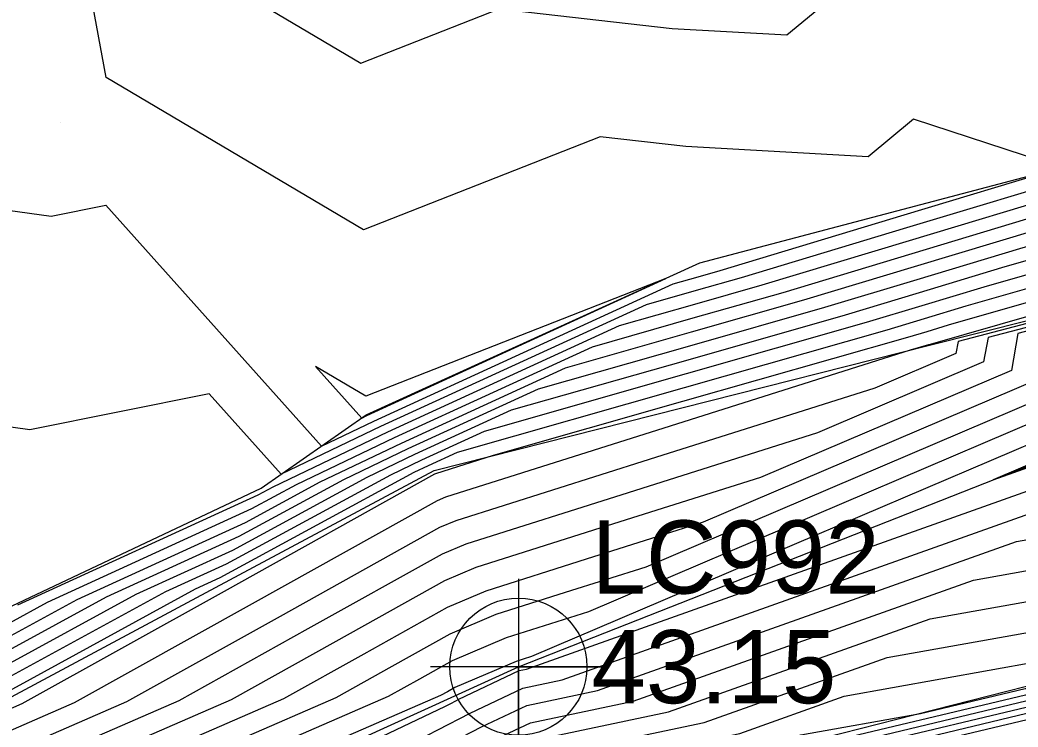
# Model space of a CAD drawing. Extents: x 2188792 to 2191981, y 386090 to 389710.
# Drawn here: x 2190178.31 to 2190212.42, y 387929.77 to 387953.95 of the extents above; entities that cross this region are included whole.
import ezdxf

# ---------------------------------------------------------------- set-up
doc = ezdxf.new("R2010")
doc.units = 0
for name, color, linetype in [('DTM Contours Major', 7, 'Continuous'), ('DTM Contours Minor', 7, 'Continuous'), ('Exist DTM Breakline Underwater', 7, 'Continuous'), ('Exist DTM Breakline Underwater Cogo Elevation', 7, 'Continuous'), ('Exist DTM Breakline Underwater Cogo Number', 7, 'Continuous'), ('Exist DTM Breakline Underwater Cogo Point CELL', 7, 'Continuous'), ('Exist DTM QL2 LIDAR Elevation Point', 7, 'Continuous'), ('PH Exist DTM Breakline', 7, 'Continuous')]:
    doc.layers.add(name, color=color, linetype=linetype)

msp = doc.modelspace()

# ---------------------------------------------------------------- linework, layer by layer
at = {"layer": 'DTM Contours Major'}
for points in [[(2190238.761, 387953.476), (2190238.236, 387953.33), (2190231.049, 387951.931), (2190229.826, 387951.794), (2190223.241, 387950.56), (2190223.252, 387950.255), (2190221.331, 387949.704), (2190216.099, 387948.12), (2190213.685, 387947.428), (2190208.783, 387945.95), (2190204.376, 387944.62), (2190201.304, 387943.745), (2190197.863, 387942.764), (2190191.097, 387939.659), (2190187.751, 387938.056), (2190186.22, 387937.225), (2190179.234, 387934.025), (2190177.951, 387933.325)], [(2190241.141, 387952.366), (2190236.279, 387951.015), (2190233.163, 387950.409), (2190227.76, 387949.804), (2190225.079, 387949.301), (2190225.113, 387948.341), (2190219.055, 387946.601), (2190217.247, 387946.054), (2190210.637, 387944.16), (2190209.214, 387943.73), (2190207.934, 387943.344), (2190201.011, 387941.371), (2190193.254, 387939.16), (2190192.262, 387938.705), (2190191.772, 387938.47), (2190185.14, 387934.868), (2190184.293, 387934.48), (2190177.559, 387930.807)], [(2190243.465, 387950.942), (2190236.16, 387948.641), (2190229.647, 387946.589), (2190224.024, 387945.428), (2190217.646, 387943.561), (2190216.945, 387944.409), (2190212.415, 387943.221), (2190212.19, 387941.963), (2190203.611, 387938.301), (2190198.377, 387936.644), (2190193.887, 387935.221), (2190192.821, 387934.763), (2190189.103, 387932.693), (2190185.528, 387930.702), (2190172.055, 387924.838)], [(2190239.074, 387945.134), (2190217.532, 387940.686), (2190217.208, 387940.591), (2190216.993, 387940.852), (2190216.931, 387940.51), (2190211.569, 387938.221), (2190216.791, 387940.078), (2190217.034, 387940.122), (2190217.401, 387939.598), (2190217.247, 387940.318), (2190217.643, 387940.231), (2190218.033, 387940.301), (2190242.904, 387941.223)], [(2190174.772, 387918.95), (2190187.655, 387925.086), (2190191.189, 387926.924), (2190194.861, 387928.834), (2190195.881, 387929.317), (2190200.477, 387930.285), (2190209.419, 387933.465), (2190214.208, 387934.324), (2190215.059, 387933.111), (2190219.916, 387934.166), (2190219.005, 387935.394), (2190218.404, 387938.199), (2190226.213, 387936.479), (2190233.879, 387937.854), (2190238.048, 387938.009), (2190238.066, 387937.699), (2190244.835, 387939.381)], [(2190175.323, 387915.538), (2190181.724, 387918.921), (2190182.593, 387919.342), (2190188.861, 387922.648), (2190189.628, 387923.046), (2190195.733, 387926.265), (2190196.621, 387926.724), (2190203.158, 387928.251), (2190204.711, 387928.684), (2190206.464, 387929.173), (2190212.686, 387930.663), (2190215.555, 387930.653), (2190220.883, 387931.821), (2190224.858, 387931.651), (2190229.111, 387932.482), (2190232.668, 387933.178), (2190238.216, 387935.813), (2190241.557, 387936.557)]]:
    msp.add_lwpolyline(points, dxfattribs=at)
at = {"layer": 'DTM Contours Minor'}
for points in [[(2190208.525, 387947.281), (2190213.89, 387948.9), (2190208.847, 387950.558), (2190207.29, 387949.272), (2190201.069, 387949.623), (2190198.133, 387949.956), (2190190.044, 387946.776), (2190181.258, 387951.986), (2190179.765, 387960.073)], [(2190184.826, 387955.515), (2190189.959, 387952.472), (2190194.684, 387954.329), (2190200.594, 387953.658), (2190204.514, 387953.437), (2190209.678, 387957.701)], [(2190227.6, 387957.129), (2190234.774, 387953.043), (2190230.626, 387952.236), (2190230.239, 387952.193), (2190222.873, 387950.812), (2190222.879, 387950.638), (2190221.786, 387950.324), (2190215.869, 387948.533), (2190214.294, 387948.082), (2190208.697, 387946.394), (2190203.664, 387944.875), (2190201.363, 387944.219), (2190198.785, 387943.484), (2190190.864, 387939.85), (2190186.947, 387937.973), (2190186.437, 387937.696), (2190178.222, 387933.934)], [(2190149.752, 387955.21), (2190140.061, 387950.046), (2190143.481, 387946.538), (2190148.473, 387940.365), (2190144.823, 387935.32), (2190139.837, 387929.999), (2190143.707, 387917.215), (2190148.398, 387918.499), (2190151.676, 387919.993), (2190159.372, 387924.657), (2190150.776, 387939.385), (2190150.697, 387939.981), (2190169.786, 387948.252), (2190170.884, 387948.414), (2190179.374, 387947.236), (2190181.243, 387947.61), (2190188.609, 387939.375), (2190190.398, 387940.232), (2190200.628, 387944.926), (2190201.48, 387945.169), (2190202.241, 387945.386), (2190208.525, 387947.281)], [(2190216.682, 387955.398), (2190221.76, 387953.676), (2190225.395, 387951.605), (2190222.506, 387951.063), (2190222.507, 387951.021), (2190222.242, 387950.945), (2190215.639, 387948.946), (2190214.904, 387948.736), (2190208.611, 387946.838), (2190202.953, 387945.131), (2190201.422, 387944.694), (2190199.706, 387944.205), (2190190.631, 387940.041), (2190187.233, 387938.413), (2190184.778, 387941.158), (2190178.644, 387939.932), (2190174.81, 387940.464)], [(2190239.237, 387953.254), (2190237.845, 387952.867), (2190231.472, 387951.627), (2190229.413, 387951.396), (2190223.608, 387950.308), (2190223.624, 387949.873), (2190220.876, 387949.083), (2190216.328, 387947.707), (2190213.075, 387946.775), (2190208.869, 387945.506), (2190205.087, 387944.365), (2190201.246, 387943.27), (2190196.941, 387942.043), (2190191.33, 387939.468), (2190188.555, 387938.139), (2190186.004, 387936.753), (2190180.245, 387934.116), (2190177.873, 387932.822)], [(2190239.713, 387953.032), (2190237.453, 387952.404), (2190231.894, 387951.323), (2190228.999, 387950.998), (2190223.976, 387950.056), (2190223.996, 387949.49), (2190220.421, 387948.463), (2190216.558, 387947.293), (2190212.465, 387946.121), (2190208.955, 387945.062), (2190205.799, 387944.11), (2190201.187, 387942.795), (2190196.019, 387941.322), (2190191.563, 387939.277), (2190189.359, 387938.222), (2190185.788, 387936.282), (2190181.257, 387934.207), (2190177.794, 387932.318)], [(2190240.665, 387952.588), (2190236.67, 387951.478), (2190232.74, 387950.714), (2190228.173, 387950.202), (2190224.711, 387949.553), (2190224.741, 387948.724), (2190219.51, 387947.221), (2190217.017, 387946.467), (2190211.246, 387944.813), (2190209.128, 387944.174), (2190207.222, 387943.599), (2190201.07, 387941.846), (2190194.175, 387939.88), (2190192.029, 387938.896), (2190190.968, 387938.387), (2190185.356, 387935.339), (2190183.281, 387934.389), (2190177.638, 387931.31)], [(2190240.189, 387952.81), (2190237.062, 387951.941), (2190232.317, 387951.018), (2190228.586, 387950.6), (2190224.344, 387949.805), (2190224.368, 387949.107), (2190219.965, 387947.842), (2190216.788, 387946.88), (2190211.856, 387945.467), (2190209.041, 387944.618), (2190206.51, 387943.855), (2190201.128, 387942.32), (2190195.097, 387940.601), (2190191.796, 387939.086), (2190190.164, 387938.304), (2190185.572, 387935.811), (2190182.269, 387934.298), (2190177.716, 387931.814)], [(2190241.616, 387952.144), (2190235.887, 387950.552), (2190233.585, 387950.105), (2190227.346, 387949.406), (2190225.447, 387949.05), (2190225.485, 387947.958), (2190218.6, 387945.98), (2190217.477, 387945.64), (2190210.027, 387943.506), (2190209.3, 387943.286), (2190208.645, 387943.089), (2190200.952, 387940.896), (2190194.479, 387939.051), (2190192.511, 387938.427), (2190192.475, 387938.412), (2190185.286, 387934.409), (2190178.375, 387930.561), (2190176.934, 387929.934)], [(2190242.092, 387951.922), (2190235.496, 387950.09), (2190234.008, 387949.8), (2190226.933, 387949.008), (2190225.814, 387948.798), (2190225.858, 387947.575), (2190218.144, 387945.36), (2190217.706, 387945.227), (2190209.418, 387942.852), (2190209.386, 387942.842), (2190209.357, 387942.834), (2190208.733, 387942.656), (2190200.532, 387940.058), (2190192.855, 387937.626), (2190192.561, 387937.5), (2190186.241, 387933.98), (2190180.163, 387930.596), (2190175.714, 387928.66)], [(2190243.044, 387951.478), (2190237.242, 387949.866), (2190234.984, 387949.155), (2190227.762, 387946.88), (2190225.322, 387946.376), (2190217.734, 387944.155), (2190217.33, 387944.644), (2190211.391, 387943.086), (2190211.242, 387942.254), (2190205.567, 387939.832), (2190199.096, 387937.782), (2190193.543, 387936.023), (2190192.735, 387935.675), (2190188.149, 387933.122), (2190183.739, 387930.667), (2190173.274, 387926.112)], [(2190242.568, 387951.7), (2190235.104, 387949.627), (2190234.431, 387949.496), (2190226.52, 387948.609), (2190226.182, 387948.546), (2190226.23, 387947.193), (2190222.987, 387946.261), (2190217.822, 387944.749), (2190217.715, 387944.878), (2190210.367, 387942.951), (2190210.294, 387942.545), (2190207.523, 387941.362), (2190199.814, 387938.92), (2190193.199, 387936.824), (2190192.648, 387936.588), (2190187.195, 387933.551), (2190181.951, 387930.632), (2190174.494, 387927.386)], [(2190243.847, 387950.177), (2190237.337, 387948.126), (2190231.533, 387946.298), (2190222.725, 387944.479), (2190217.559, 387942.967), (2190216.56, 387944.175), (2190213.439, 387943.356), (2190213.139, 387941.672), (2190201.654, 387936.771), (2190197.659, 387935.505), (2190194.231, 387934.419), (2190192.908, 387933.851), (2190190.057, 387932.264), (2190187.316, 387930.737), (2190170.835, 387923.564)], [(2190244.228, 387949.412), (2190238.513, 387947.612), (2190233.418, 387946.007), (2190221.427, 387943.531), (2190217.471, 387942.373), (2190216.176, 387943.941), (2190214.464, 387943.492), (2190214.087, 387941.382), (2190199.698, 387935.241), (2190196.941, 387934.367), (2190194.575, 387933.618), (2190192.995, 387932.939), (2190191.011, 387931.835), (2190189.104, 387930.773), (2190169.615, 387922.29)], [(2190239.69, 387947.098), (2190235.303, 387945.716), (2190220.129, 387942.582), (2190217.384, 387941.779), (2190215.791, 387943.706), (2190215.488, 387943.627), (2190215.035, 387941.091), (2190197.741, 387933.71), (2190196.222, 387933.229), (2190194.919, 387932.816), (2190193.081, 387932.027), (2190191.965, 387931.405), (2190190.892, 387930.808), (2190168.395, 387921.016)], [(2190240.867, 387946.584), (2190237.189, 387945.425), (2190218.831, 387941.634), (2190217.296, 387941.185), (2190216.273, 387942.423), (2190215.983, 387940.8), (2190195.785, 387932.18), (2190195.504, 387932.091), (2190195.263, 387932.015), (2190193.168, 387931.115), (2190192.919, 387930.976), (2190192.68, 387930.843), (2190167.175, 387919.742)], [(2190190.165, 387940.422), (2190200.385, 387945.112), (2190190.129, 387941.081), (2190188.405, 387942.103), (2190189.985, 387940.336), (2190190.165, 387940.422)], [(2190167.739, 387918.52), (2190192.822, 387930.467), (2190193.059, 387930.59), (2190193.305, 387930.718), (2190195.37, 387931.698), (2190195.617, 387931.749), (2190215.316, 387938.755), (2190216.469, 387938.962), (2190218.21, 387936.481), (2190217.478, 387939.895), (2190219.357, 387939.481), (2190221.202, 387939.812), (2190241.932, 387940.58)], [(2190169.497, 387918.627), (2190191.531, 387929.122), (2190192.591, 387929.674), (2190193.694, 387930.247), (2190195.498, 387931.103), (2190196.832, 387931.383), (2190213.842, 387937.433), (2190215.903, 387937.803), (2190217.685, 387935.264), (2190218.699, 387935.484), (2190218.509, 387935.741), (2190217.71, 387939.471), (2190221.071, 387938.73), (2190224.371, 387939.322), (2190240.961, 387939.937)], [(2190171.256, 387918.735), (2190190.239, 387927.777), (2190192.124, 387928.757), (2190194.083, 387929.776), (2190195.625, 387930.507), (2190198.047, 387931.017), (2190212.368, 387936.11), (2190215.338, 387936.643), (2190216.809, 387934.546), (2190219.105, 387935.045), (2190218.674, 387935.625), (2190217.941, 387939.047), (2190222.785, 387937.98), (2190227.54, 387938.833), (2190239.99, 387939.294)], [(2190176.531, 387919.057), (2190186.364, 387923.741), (2190190.722, 387926.007), (2190195.25, 387928.362), (2190196.009, 387928.722), (2190201.693, 387929.919), (2190207.945, 387932.143), (2190213.642, 387933.165), (2190214.184, 387932.394), (2190220.321, 387933.727), (2190219.17, 387935.278), (2190218.635, 387937.775), (2190227.927, 387935.728), (2190237.048, 387937.365), (2190237.077, 387937.366), (2190237.077, 387937.364), (2190237.167, 387937.387), (2190244.751, 387939.075)], [(2190173.014, 387918.842), (2190188.947, 387926.431), (2190191.657, 387927.841), (2190194.472, 387929.305), (2190195.753, 387929.912), (2190199.262, 387930.651), (2190210.894, 387934.788), (2190214.773, 387935.484), (2190215.934, 387933.829), (2190219.51, 387934.606), (2190218.839, 387935.509), (2190218.172, 387938.623), (2190224.499, 387937.229), (2190230.71, 387938.344), (2190239.019, 387938.652)], [(2190178.289, 387919.165), (2190185.072, 387922.396), (2190190.254, 387925.091), (2190195.639, 387927.891), (2190196.136, 387928.127), (2190202.908, 387929.553), (2190206.471, 387930.82), (2190213.077, 387932.005), (2190213.308, 387931.676), (2190220.727, 387933.288), (2190219.335, 387935.163), (2190218.866, 387937.352), (2190228.468, 387935.236), (2190223.124, 387933.808), (2190228.954, 387934.948), (2190235.975, 387936.321), (2190237.355, 387936.977), (2190243.953, 387938.445)], [(2190173.758, 387916.019), (2190180.047, 387919.272), (2190183.78, 387921.05), (2190189.787, 387924.174), (2190196.028, 387927.42), (2190196.264, 387927.532), (2190204.123, 387929.187), (2190204.997, 387929.497), (2190209.081, 387930.23), (2190212.659, 387931.087), (2190212.983, 387931.086), (2190220.82, 387932.805), (2190221.99, 387932.754), (2190229.006, 387934.126), (2190234.873, 387935.273), (2190237.642, 387936.589), (2190243.154, 387937.816)], [(2190174.734, 387915.723), (2190181.806, 387919.38), (2190182.488, 387919.705), (2190189.319, 387923.258), (2190192.136, 387924.723), (2190196.323, 387926.931), (2190196.401, 387926.971), (2190203.97, 387928.739), (2190204.595, 387928.913), (2190205.302, 387929.11), (2190212.673, 387930.875), (2190214.269, 387930.87), (2190220.852, 387932.313), (2190223.424, 387932.203), (2190229.059, 387933.304), (2190233.77, 387934.226), (2190237.929, 387936.201), (2190242.356, 387937.186)], [(2190175.67, 387915.423), (2190181.112, 387918.299), (2190183.101, 387919.263), (2190188.402, 387922.059), (2190189.991, 387922.882), (2190195.144, 387925.599), (2190196.84, 387926.478), (2190202.346, 387927.764), (2190204.826, 387928.455), (2190207.627, 387929.236), (2190212.7, 387930.451), (2190216.841, 387930.436), (2190220.915, 387931.33), (2190226.292, 387931.099), (2190229.164, 387931.66), (2190231.565, 387932.13), (2190238.503, 387935.425), (2190240.759, 387935.927)], [(2190176.017, 387915.308), (2190180.5, 387917.677), (2190183.609, 387919.184), (2190187.944, 387921.47), (2190190.353, 387922.718), (2190194.554, 387924.933), (2190197.06, 387926.231), (2190201.535, 387927.276), (2190204.941, 387928.226), (2190208.789, 387929.299), (2190212.714, 387930.239), (2190218.127, 387930.22), (2190220.946, 387930.838), (2190227.727, 387930.547), (2190229.217, 387930.839), (2190230.462, 387931.082), (2190238.79, 387935.037)], [(2190176.364, 387915.193), (2190179.888, 387917.055), (2190184.117, 387919.105), (2190187.486, 387920.881), (2190190.715, 387922.554), (2190193.964, 387924.267), (2190197.28, 387925.985), (2190200.723, 387926.789), (2190205.056, 387927.997), (2190209.951, 387929.362), (2190212.727, 387930.027), (2190219.412, 387930.003), (2190220.977, 387930.346), (2190229.161, 387929.995), (2190229.269, 387930.017), (2190229.36, 387930.034), (2190239.077, 387934.649)]]:
    msp.add_lwpolyline(points, dxfattribs=at)
at = {"layer": 'Exist DTM Breakline Underwater'}
msp.add_lwpolyline([(2190165.897, 387918.407), (2190195.341, 387931.833), (2190217.185, 387940.432), (2190258.084, 387945.215), (2190309.218, 387932.714), (2190343.089, 387929.481), (2190375.21, 387918.126)], dxfattribs=at)
at = {"layer": 'Exist DTM Breakline Underwater Cogo Point CELL'}
msp.add_lwpolyline([(2190195.341, 387934.833), (2190195.341, 387928.833), (2190195.341, 387931.833), (2190198.341, 387931.833), (2190192.341, 387931.833)], dxfattribs=at)
msp.add_circle((2190195.341, 387931.833), 2.344, dxfattribs=at)
at = {"layer": 'Exist DTM QL2 LIDAR Elevation Point'}
msp.add_line((2190179.694, 387950.438), (2190179.694, 387950.438), dxfattribs=at)
at = {"layer": 'PH Exist DTM Breakline'}
for points in [[(2190109.829, 387900.589), (2190117.728, 387904.556), (2190125.627, 387908.523), (2190133.526, 387912.49), (2190141.824, 387916.341), (2190150.122, 387920.192), (2190161.927, 387925.89), (2190169.542, 387929.904), (2190178.043, 387933.918), (2190186.545, 387937.932), (2190190.139, 387940.444), (2190201.538, 387945.638), (2190208.488, 387947.473), (2190215.438, 387949.309), (2190222.388, 387951.144), (2190230.431, 387952.377), (2190238.473, 387953.61)], [(2190140.155, 387912.651), (2190146.114, 387916.254), (2190154.091, 387919.685), (2190162.069, 387923.115), (2190170.047, 387926.546), (2190177.519, 387930.544), (2190184.99, 387934.543), (2190192.462, 387938.541), (2190200.926, 387940.681), (2190209.39, 387942.822), (2190217.853, 387944.963), (2190226.317, 387947.103), (2190234.78, 387949.244), (2190243.244, 387951.384)], [(2190245.208, 387939.435), (2190237.07, 387937.362), (2190228.932, 387935.288), (2190220.794, 387933.215), (2190212.656, 387931.141), (2190204.518, 387929.068), (2190196.38, 387926.994), (2190189.289, 387923.199), (2190182.199, 387919.404), (2190175.109, 387915.609), (2190167.285, 387912.244), (2190159.46, 387908.88), (2190151.636, 387905.515), (2190141, 387899.082), (2190133.702, 387893.484)]]:
    msp.add_lwpolyline(points, dxfattribs=at)

# ---------------------------------------------------------------- texts
at = {"layer": 'Exist DTM Breakline Underwater Cogo Elevation'}
msp.add_text('43.15', height=2.5, dxfattribs=at).set_placement((2190197.841, 387930.583))
at = {"layer": 'Exist DTM Breakline Underwater Cogo Number'}
msp.add_text('LC992', height=2.5, dxfattribs=at).set_placement((2190197.841, 387934.333))

doc.saveas('drawing.dxf')
